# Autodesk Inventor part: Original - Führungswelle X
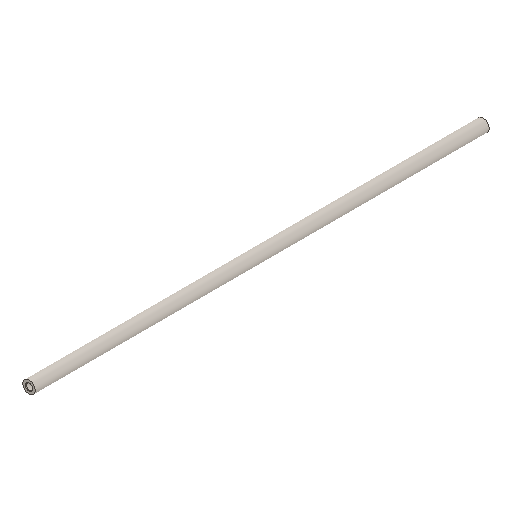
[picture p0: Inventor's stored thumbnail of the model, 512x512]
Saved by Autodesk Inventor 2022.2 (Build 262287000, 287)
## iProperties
Created: 2024-09
Part Number: Original - Führungswelle X
Material: Generico
Document SubType Name: Modeling
Designer: 18907419
Density: 1 g/cm^3
Appearance: Default
Author: 18907419
Revision Number: ANY
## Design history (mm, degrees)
feature "Fase1"
node "Solido1"
